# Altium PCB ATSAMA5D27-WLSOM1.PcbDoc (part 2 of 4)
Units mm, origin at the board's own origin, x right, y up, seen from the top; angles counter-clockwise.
Board outline 40.8 x 40.8 mm, 6 copper layers (L1 - Top, L2 - GND, L3 - Signal, L4 - Signal, L5 - PWR, L6 - Bottom), stack 1.144 mm thick; 196 components, 221 nets, 1038 pads, 713 vias.
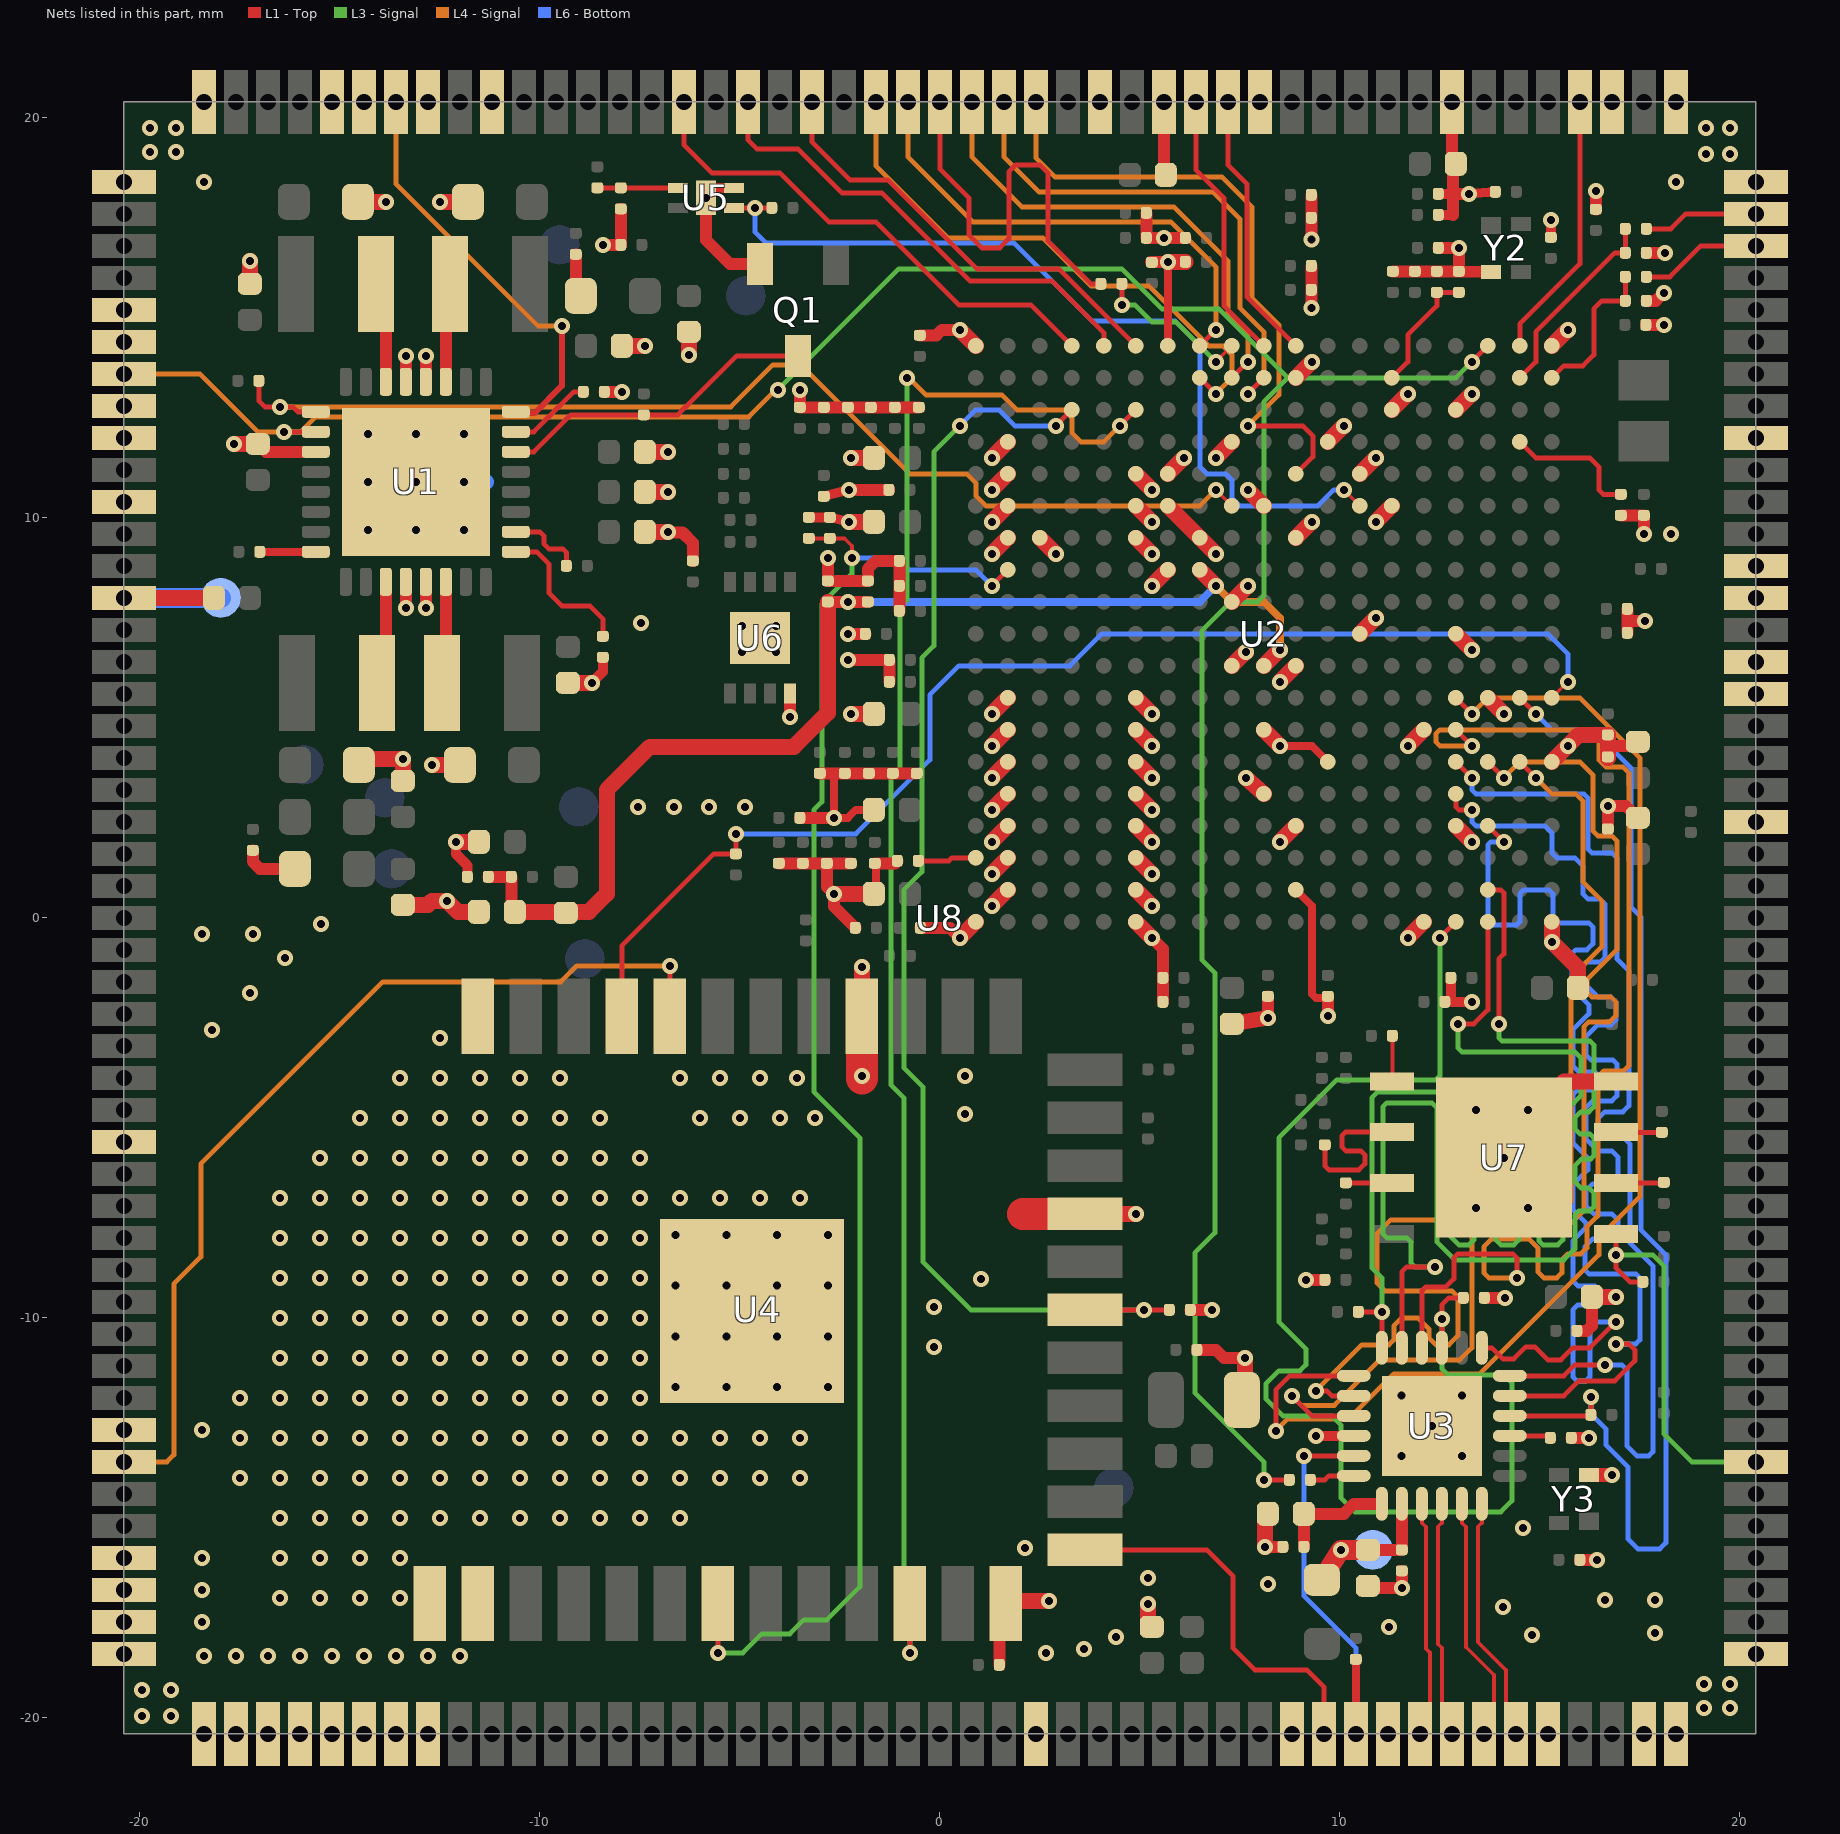
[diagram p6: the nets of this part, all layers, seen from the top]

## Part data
C1 C3 C4 C6 C8 C10 C12 C13 C14 C15 C20 C21 C22 C23 C25 C64 C65 C82 C97 C98 C99 C100 C101 C105: library part CAP1684, "Capacitor", Manufacturer 1="TDK Corporation", Manufacturer Part Number 1=C1005X5R1A475K050BC, Operating Temperature="-55C to 85C", Package=0402, Supplier Part Number 1=445-13820-1-ND, Temperature Coeffcient=X5R, Tolerance=10%, Voltage=10V
C2 C5 C7 C9: library part CAP1648, "Capacitor", Manufacturer 1="TDK Corporation", Manufacturer 2="Murata Electronics North America", Manufacturer Part Number 1=C1608X5R1A226M080AC, Manufacturer Part Number 2=GRM188R61A226ME15D, Operating Temperature="-55C to +85C", Package=0603, Supplier Part Number 1=2525091, Temperature Coeffcient=X5R, Tolerance=20%, Voltage=10V
C11 C16 C24 C26 C27 C28 C29 C30 C31 C32 C33 C34 C35 C36 C37 C38 C39 C40 C41 C42 C43 C44 C45 C46 C47 C48 C49 C50 C51 C52 C53 C54 C55 C56 C57 C58 C59 C60 C61 C62 C63 C66 C67 C68 C69 C70 C71 C72 C73 C74 C75 C76 C77 C78 C79 C80 C81 C83 C85 C87 C89 C90 C92 C93 C94 C95 C96: library part CAP2003, "Capacitor", Manufacturer 1=KEMET, Manufacturer 2="Murata Electronics North America", Manufacturer 3=Yageo, Manufacturer Part Number 1=C0201C104K9PACTU, Manufacturer Part Number 2=GRM033R60J104KE19D, Manufacturer Part Number 3=CC0201KRX5R5BB104, Operating Temperature="-55C to +85C", Package=0201, Supplier Part Number 1=399-7743-1-ND, Temperature Coeffcient=X5R, Tolerance=10%, Voltage=6.3V
C17: library part CAP1453, "Capacitor", Manufacturer 1="TDK Corporation", Manufacturer Part Number 1=C0603C0G1E100D030BA, Operating Temperature="-55C to +125C", Package=0201, Supplier Part Number 1=445-4651-2-ND, Temperature Coeffcient=C0G, Tolerance=0.5pF, Voltage=25V
C18 C19: library part CAP1996, "Capacitor", Manufacturer 1="TDK Corporation", Manufacturer 2="Murata Electronics", Manufacturer Part Number 1=CGA1A2C0G1H080D030BA, Manufacturer Part Number 2=GRM0335C1H8R0BA01D, Operating Temperature="-55C to +125C", Package=0201, Supplier Part Number 1=445-12057-1-ND, Temperature Coeffcient=C0G, Tolerance=0.1pF, Voltage=50V
C84: library part CAP1468, "Capacitor", Manufacturer 1="TDK Corporation", Manufacturer 2="Murata Electronics North America", Manufacturer Part Number 1=C1005X7S1A225K050BC, Manufacturer Part Number 2=GRM155C71A225KE11J, Operating Temperature="-55C to +125C", Package=0402, Supplier Part Number 1=445-9097-1-ND, Temperature Coeffcient=X7S, Tolerance=10%, Voltage=10V
C86 C88: library part CAP1766, "Capacitor", Manufacturer 1=Yageo, Manufacturer Part Number 1=CC0402MRX5R5BB106, Operating Temperature="-55°C ~ 85°C", Package=0402, Supplier Part Number 1=311-1729-1-ND, Temperature Coeffcient=X5R, Tolerance=20%, Voltage=6.3V
C91: library part CAP2000, "Capacitor", Manufacturer 1="Murata Electronics North America", Manufacturer 2="Taiyo Yuden", Manufacturer 3=Murata, Manufacturer 4=TDK, Manufacturer Part Number 1=GRM21BR61A476ME15L, Manufacturer Part Number 2=LMK212BBJ476MG-T, Manufacturer Part Number 3=GRM21BR61A476ME15K, Manufacturer Part Number 4=C2012X5R1A476M125AC, Operating Temperature="-55C to +85C", Package=0805, Supplier Part Number 1=490-9961-1-ND, Temperature Coeffcient=X5R, Tolerance=20%, Voltage=10V
C102 C103 C104: library part CAP1450, "Capacitor", Manufacturer 1="Murata Electronics North America", Manufacturer Part Number 1=GRM0335C1E101JA01D, Operating Temperature="-55C to 125C", Package=0201, Supplier Part Number 1=490-3160-1-ND, Temperature Coeffcient=NP0, Tolerance=5%, Voltage=25V
C106 C107: library part CAP1201, "Capacitor", Manufacturer 1=Murata, Manufacturer Part Number 1=GRM033R61A103KA01D, Operating Temperature="-55C to +85C", Package=0201, Supplier Part Number 1=490-3166-2-ND, Temperature Coeffcient=X5R, Tolerance=10%, Voltage=10V
FB1: library part IND1453, "FERRITE 180R 1.5A SMD 0603", Manufacturer 1="Murata Electronics North America", Manufacturer Part Number 1=BLM18PG181SN1D, Operating Temperature="-55C to +125C", Package=0603, Saturation Current=1.5A, Supplier Part Number 1=490-5263-1-ND, Test Frequency=100MHz
FB2: library part IND1453, Manufacturer 1="Murata Electronics North America", Manufacturer Part Number 1=BLM18PG181SN1D, Operating Temperature="-55C to +125C", Package=0603, Saturation Current=1.5A, Supplier Part Number 1=490-5263-1-ND, Test Frequency=100MHz
FB3 FB4: library part IND1642, Manufacturer 1="Wurth Electronics", Manufacturer Part Number 1=742792731, Operating Temperature="-55C to +125C", Package=0402, RMS Current=1.2A, Supplier Part Number 1=732-2362-1-ND, Test Frequency=100MHz
L1 L3 L4 L6: library part IND1335, Manufacturer 1="Murata Electronics North America", Manufacturer Part Number 1=DFE252012P-1R5M{}P2, Package=1008, RMS Current=3.5A, Supplier Part Number 1=490-10648-6-ND, Test Frequency=1MHz
L2 L5: library part IND1213, Manufacturer 1="TDK Corporation", Manufacturer Part Number 1=MLZ1608N100LT000, Operating Temperature="-55C to +125C", Package=0603, RMS Current=300mA, Saturation Current=60mA, Supplier Part Number 1=445-6755-1-ND, Test Frequency=2MHz
Q1: library part TRA1147, "Transistor MOS", Current=220mA, Drain to Source Voltage=50V, Gate to Source Voltage=1.3V, Manufacturer 1=Fairchild, Manufacturer Part Number 1=BSS138, Operating Temperature="-55C to +150C", Package=SOT-23-3, Power=360mW, Supplier Part Number 1=9845330
R1 R27: library part RES1582, Manufacturer 1="Panasonic Electronic Components", Manufacturer Part Number 1=ERJ-1GEF1003C, Operating Temperature="-55C to +125C", Package=0201, Power=1/20W, Supplier Part Number 1=P100KABCT-ND, Temperature Coeffcient=200ppm/C, Tolerance=1%, Voltage=15V
R2 R6 R11 R23 R24 R26 R32 R34 R35 R36 R37 R38 R39 R40 R41: library part RSMT1252, Manufacturer 1=Yageo, Manufacturer Part Number 1=RC0201FR-0710KL, Operating Temperature="-55 to +125C", Package=0201, Power=1/20W, Supplier Part Number 1=311-10.0KMCT-ND, Temperature Coeffcient=200pm/C, Tolerance=1%, Voltage=25V
R3 R20 R21: library part RES1588, Manufacturer 1="Panasonic Electronic Components", Manufacturer Part Number 1=ERJ-1GEF1001C, Operating Temperature="-55°C to 125°C", Package=0201, Power=1/20W, Supplier Part Number 1=P1.00KABTR-ND, Tolerance=1%, Voltage=25V
R4 R8: library part RSMT1253, Manufacturer 1=Yageo, Manufacturer Part Number 1=RC0201JR-072R2L, Operating Temperature="-55C to +125C", Package=0201, Power=1/20W, Supplier Part Number 1=YAG2886CT-ND, Temperature Coeffcient="-100/+350 ppm/C", Tolerance=5%, Voltage=25V
R5 R25 R58 R60: library part RSMT1240, Current=0.5A, Manufacturer 1="Panasonic Electronic Components", Manufacturer Part Number 1=ERJ-1GN0R00C, Operating Temperature="-55C to +125C", Package=0201, Power=1/20W, Supplier Part Number 1=P15979CT-ND, Voltage=50V
R9 R10: library part RES2022, Manufacturer 1=Yageo, Manufacturer Part Number 1=RC0402FR-071K5L, Operating Temperature="-55C to +155C", Package=0402, Power=1/16W, Supplier Part Number 1=311-1.50KLRCT-ND, Temperature Coeffcient=100ppm/°C, Tolerance=1%
R12: library part RES2053, Manufacturer 1=Yageo, Manufacturer Part Number 1=RC0201FR-075K62L, Operating Temperature="-55C to +125C", Package=0201, Power=1/20W, Supplier Part Number 1=YAG2345CT-ND, Temperature Coeffcient=200ppm/C, Tolerance=1%
R13 R14 R42 R43: library part RSMT1251, Current=0.5A, Manufacturer 1="Vishay Dale", Manufacturer Part Number 1=CRCW02012K20FKED, Operating Temperature="-55C to +155C", Package=0201, Power=1/20W, Supplier Part Number 1=541-2.20KAABCT-ND, Temperature Coeffcient=100ppm/C, Tolerance=1%, Voltage=25V
R15 R16 R17 R18 R44 R45 R46 R47 R48 R49 R50 R51 R52 R53 R59: library part RES1473, Manufacturer 1="Panasonic Electronic Components", Manufacturer Part Number 1=ERJ-1GEF22R0C, Operating Temperature="-55C to +125C", Package=0201, Power=1/20W, Supplier Part Number 1=P22.0ABCT-ND, Tolerance=1%, Voltage=25V
R19: library part RSMT1249, Current=0.5A, Manufacturer 1=Yageo, Manufacturer Part Number 1=RC0201FR-07240RL, Operating Temperature="-55C to +125C", Package=0201, Power=1/20W, Supplier Part Number 1=YAG2528CT-ND, Temperature Coeffcient=200ppm, Tolerance=1%, Voltage=25V
R22: library part RSMT1250, Current=0.5A, Manufacturer 1=Yageo, Manufacturer Part Number 1=AC0201FR-076K49L, Operating Temperature="-55C to +155C", Package=0201, Power=1/20W, Supplier Part Number 1=YAG5236CT-ND, Temperature Coeffcient=200ppm, Tolerance=1%, Voltage=25V
R28 R29 R30 R31: library part RES2264, Manufacturer 1=Yageo, Manufacturer Part Number 1=RC0201FR-0768KL, Operating Temperature="-55C to +125C", Package=0201, Power=1/20W, Supplier Part Number 1=YAG2772CT-ND, Temperature Coeffcient=200ppm/C, Tolerance=1%, Voltage=25V
R55 R56 R57: library part RES2175, Current=0.5A, Manufacturer 1=Yageo, Manufacturer Part Number 1=RC0201FR-07100RL, Operating Temperature="-55C to +125C", Package=0201, Power=1/20W, Supplier Part Number 1=311-100MCT-ND, Temperature Coeffcient=200ppm/C, Tolerance=1%, Voltage=25V
TP1 TP2 TP3 TP4 TP6 TP7 TP8 TP9 TP10 TP11: library part CON1759, "Test Point"
U1: library part MIC8644, Manufacturer 1="Microchip Technology", Manufacturer Part Number 1=MCP16502AC-E/S8B
U2: library part MIC8130, "SAMA5D2 MPU with 2Gb LPDDR2 x32 TFBGA-361", Manufacturer 1="Microchip Technology / Atmel", Manufacturer Part Number 1=ATSAMA5D27C-LD2G-CU, PackageType=TFBGA-361, PackageWidth=16x16x1.2mm, Supplier Part Number 1=ATSAMA5D27C-LD2G-CU-ND, TempRange="-40C to +85C"
U3: library part MIC7404, Manufacturer 1="Microchip Technology", Manufacturer Part Number 1=KSZ8081RNAIA-TR, Supplier Part Number 1=576-4174-1-ND
U4: library part MIC8126, FrequencyRange="2.412-2.472 MHz", Manufacturer 1="Microchip Technology", Manufacturer Part Number 1=ATWILC3000-MR110UA, PowerRX="84mA (802.11n MCS7)", PowerTX="253mA (802.11n MCS7)", RfPower=0, Supplier Part Number 1=ATWILC3000-MR110UA-ND
U5: library part MIC8024, Manufacturer 1="Microchip Technology", Manufacturer Part Number 1=MIC842NYMT-T5, PackageType=UDFN, PackageWidth=1.2x1.6x0.6mm, Supplier Part Number 1=576-4506-1-ND, TempRange="-40C to +85C"
U6: library part MIC8843, Manufacturer 1="Microchip Technology Inc", Manufacturer Part Number 1=ATECC608A-TNGTLSU-C, Supplier Part Number 1=150-ATECC608A-TNGTLSU-C-ND
U7: library part MIC8649, "SQI Serial Flash", Manufacturer 1="Microchip Technology", Manufacturer Part Number 1=SST26VF064BEUI-104I/MF, MaxClockFreq="104 MHz", OpVoltMax=3,6, OpVoltMin=2,3, PackageType=TDFN-S, PackageWidth=6x5x0.8mm, TempRange="-40C to +85C"
U8: library part WLSOM-188, "188-Castellated thru-holes, 40.80mm x 40.80mm package"
Y1: library part OSC1206, "Crystal", Load Capacitance=6pF, Manufacturer 1="NDK America, Inc.", Manufacturer Part Number 1=NX2012SA-32.768KHZ-EXS00A-MU00626, Operating Temperature="-40C to +85C", Package="2mm x 1.2mm", Supplier Part Number 1=644-1355-1-ND, Tolerance="20 ppm"
Y2: library part MIC8647, Manufacturer 1="Microchip Technology", Manufacturer Part Number 1=DSC6003HI2B-024.0000, Supplier Part Number 1=DSC6003HI2B-024.0000-ND
Y3: library part MIC8785, Manufacturer 1="Microchip Technology Inc", Manufacturer Part Number 1=DSC6102HI2B-025.000

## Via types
v1: diameter 0.4, hole 0.2, L1 - Top to L6 - Bottom, 680 vias
v2: diameter 0.4, hole 0.2, L1 - Top to L6 - Bottom, tented both sides, 17 vias
v3: diameter 0.4, hole 0.2, L1 - Top to L6 - Bottom, tented bottom, 16 vias

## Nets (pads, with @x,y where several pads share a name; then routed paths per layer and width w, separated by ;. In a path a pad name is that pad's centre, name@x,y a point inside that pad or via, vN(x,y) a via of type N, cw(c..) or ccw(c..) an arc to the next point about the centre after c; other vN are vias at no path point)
CE_WILC_PA29: R34.2 U2.U16 U4.19 | length 33.2
  L1 - Top w0.125: v1(2.9,12.3) U2.U16@3.3,12.7 ; U4.19@3.53,-9.8 U4.19@3.63,-9.8 v1@5,-9.8 ; v1@5.2,-9.8 R34.2@5.738,-9.8
  L3 - Signal w0.125: v1(0.5,12.3) -0.15,11.65 -0.15,6.8 -0.45,6.5 -0.45,1.15 -0.9,0.7 -0.9,-3.75 -0.425,-4.225 -0.425,-8.6 0.775,-9.8 v1(5.1,-9.8) ; v1@5,-9.8 v1(5.1,-9.8) ; v1@5.1,-9.75 v1(5.1,-9.8)
  L6 - Bottom w0.125: v1(0.5,12.3) 0.9,12.7 1.475,12.7 1.875,12.3 v1(2.9,12.3)
CLK_AUDIO: U2.W2 U8.145 | length 6.7
  L1 - Top w0.125: U2.W2@14.5,14.3 14.5,14.85 16,16.35 U8.145@16,20.4
COMPN: C103.2 R56.2 U2.V2 | length 5
  L1 - Top w0.125: U2.V2@14.5,13.5 14.9,13.9 14.9,14.65 16.875,16.625 C103.2@17.138,16.625 R56.2@17.138,17.225
COMPP: C102.2 R55.2 U2.V1 | length 3.9
  L1 - Top w0.125: U2.V1@15.3,13.5 15.6,13.8 16.075,13.8 16.35,14.075 16.35,15.225 16.55,15.425 C102.2@17.138,15.425 R55.2@17.138,16.025
CTS_WILC_PA26: U2.U14 U4.11 | length 40.6
  L1 - Top w0.125: v1(-0.75,-18.375) U4.11@-0.75,-17.14 ; v1(4.5,12.3) U2.U14@4.9,12.7
  L3 - Signal w0.125: v1(-0.825,13.5) -0.825,7.95 -1,7.775 -1,3.675 -1.225,3.45 -1.225,-4.175 -0.9,-4.5 -0.9,-17.6 -0.75,-17.75 v1(-0.75,-18.375) ; v1(4.5,12.3) v1@4.6,12.2
  L4 - Signal w0.125: v1(-0.825,13.5) -0.775,13.5 -0.35,13.075 1.55,13.075 1.925,12.7 3.1,12.7 3.3,12.5 3.3,12.125 3.525,11.9 4.1,11.9 v1(4.5,12.3)
DDR_VREF: C11.1 C16.2 C61.1 C62.1 R9.1 R10.2 U2.J10 U2.M12 | length 29.9
  L1 - Top w0.3: C16.2@-11.288,1.025 C11.1@-10.712,1.025 -10.712,0.237 R10.2@-10.625,0.15 ; C62.1@-2.8,7.9 v1(-2.3,7.9) C61.1@-1.8,7.9
  L1 - Top w0.4: R10.2@-10.625,0.15 -8.775,0.15 -8.325,0.6 -8.325,3.2 -7.25,4.275 -3.65,4.275 -2.8,5.125 C62.1@-2.8,7.9 ; U2.M12@6.5,8.7 v1(6.9,8.3) ; U2.J10@8.1,6.3 v1(8.5,6.7)
  L4 - Signal w0.2: v1(6.9,8.3) 7.3,7.9 8.1,7.9 8.5,7.5 v1(8.5,6.7)
  L6 - Bottom w0.2: v1(-2.3,7.9) 6.5,7.9 v1(6.9,8.3)
ETH_GMDC_PB22: U2.E4 U3.11 | length 28.1
  L1 - Top w0.125: U2.E4@12.9,3.1 12.9,2.775 12.975,2.7 v1(13.3,2.7) ; U3.11@14.25,-11.95 15.6,-11.95 15.975,-11.575 16.875,-11.575 17.375,-11.075 17.375,-10.8 17.225,-10.65 v1(16.9,-10.65)
  L6 - Bottom w0.125: v1(13.3,2.7) 13.3,2.4 13.4,2.3 15.125,2.3 15.3,2.125 15.3,1.625 15.425,1.5 15.875,1.5 16.075,1.3 16.075,0.6 16.2,0.475 16.5,0.475 16.625,0.35 16.625,-1 16.525,-1.1 16.175,-1.1 16.075,-1.2 16.075,-1.6 16.45,-1.975 16.775,-1.975 16.9,-2.1 16.9,-2.55 16.775,-2.675 16.45,-2.675 16.15,-2.975 16.15,-3.425 16.275,-3.55 16.825,-3.55 16.925,-3.65 16.925,-4.45 16.8,-4.575 16.325,-4.575 16.15,-4.75 16.15,-5.525 16.45,-5.825 16.8,-5.825 16.95,-5.975 16.95,-6.5 16.8,-6.65 16.325,-6.65 16.15,-6.825 16.15,-7.2 16.35,-7.4 16.8,-7.4 16.95,-7.55 16.95,-7.85 16.775,-8.025 16.325,-8.025 16.125,-8.225 16.125,-8.8 16.225,-8.9 17.4,-8.9 17.5,-9 17.5,-10.55 17.4,-10.65 v1(16.9,-10.65)
ETH_GMDIO_PB23: R21.1 U2.H2 U3.10 | length 30.8
  L1 - Top w0.125: U3.10@14.25,-12.45 R21.1@16.3,-12.45 ; U2.H2@14.5,5.5 v1(14.9,5.1) ; R21.1@16.275,-12.425 v1(16.275,-11.975)
  L6 - Bottom w0.125: v1(14.9,5.1) 15.3,4.7 16.325,4.7 17.275,3.75 17.275,0.275 17.525,0.025 17.525,-7.8 18.15,-8.425 18.15,-15.625 18,-15.775 17.45,-15.775 17.2,-15.525 17.2,-13.725 16.65,-13.175 16.65,-12.775 16.275,-12.4 v1(16.275,-11.975)
ETH_GRX0_PB18: U2.D3 U3.13 | length 28.3
  L1 - Top w0.125: U3.13@13.55,-10.75 13.8,-10.75 14.075,-11.025 14.35,-11.025 14.65,-10.725 14.875,-10.725 15.2,-11.05 15.525,-11.05 15.825,-10.75 16.25,-10.75 v1(16.9,-10.1) ; U2.D3@13.7,2.3 v1(14.1,1.9)
  L6 - Bottom w0.125: v1(14.1,1.9) 13.775,1.9 13.7,1.825 13.7,-0.075 13.8,-0.175 14.425,-0.175 14.5,-0.1 14.5,0.6 14.6,0.7 15.225,0.7 15.325,0.6 15.325,-0.025 15.425,-0.125 16.225,-0.125 16.325,-0.225 16.325,-0.65 16.175,-0.8 15.9,-0.8 15.8,-0.9 15.8,-1.75 16.225,-2.175 16.225,-2.4 15.825,-2.8 15.825,-3.7 15.975,-3.85 16.375,-3.85 16.475,-3.95 16.475,-4.2 16.375,-4.3 15.95,-4.3 15.825,-4.425 15.825,-5.625 16.2,-6 16.2,-6.3 15.825,-6.675 15.825,-7.3 16.15,-7.625 16.15,-7.75 15.825,-8.075 15.825,-9.075 15.95,-9.2 16.375,-9.2 16.475,-9.3 16.475,-9.575 16.375,-9.675 15.95,-9.675 15.825,-9.8 15.825,-11.475 15.925,-11.575 16.15,-11.575 16.25,-11.475 16.25,-10.2 16.35,-10.1 v1(16.9,-10.1)
ETH_GRX1_PB19: U2.F4 U3.12 | length 28.2
  L1 - Top w0.125: U2.F4@12.9,3.9 v1(13.3,3.5) ; U3.12@14.25,-11.45 15.6,-11.45 15.875,-11.175 v1(16.625,-11.175)
  L6 - Bottom w0.125: v1(13.3,3.5) 13.3,3.2 13.4,3.1 16.1,3.1 16.2,3 16.2,1.725 16.3,1.625 16.8,1.625 16.925,1.5 16.925,-1.025 17.225,-1.325 17.225,-4.7 17.075,-4.85 16.625,-4.85 16.45,-5.025 16.45,-5.375 16.575,-5.5 17.1,-5.5 17.25,-5.65 17.25,-8.125 17.825,-8.7 17.825,-13.35 17.725,-13.45 17.425,-13.45 17.175,-13.2 17.175,-11.3 17.05,-11.175 v1(16.625,-11.175)
ETH_GRXDV_PB16: R23.2 U2.A4 U3.15 | length 32.5
  L1 - Top w0.125: v1(12.5,-0.5) U2.A4@12.9,-0.1 ; U3.15@12.55,-10.75 v1(12.55,-10.025) 12.55,-9.675 12.725,-9.5 R23.2@13.088,-9.5
  L3 - Signal w0.125: v1(12.5,-0.5) 12.5,-3.95 12.4,-4.05 9.925,-4.05 8.475,-5.5 8.475,-10.1 9.15,-10.775 9.15,-11.175 9,-11.325 8.475,-11.325 8.15,-11.65 8.15,-12.025 8.575,-12.45 9.8,-12.45 10.025,-12.675 10.025,-14.5 10.375,-14.85 14.025,-14.85 14.3,-14.575 14.3,-11.625 14.1,-11.425 12.7,-11.425 12.55,-11.275 v1(12.55,-10.025)
ETH_GRXER_PB17: U2.B3 U3.17 | length 29.8
  L1 - Top w0.125: U3.17@11.55,-10.75 11.55,-8.85 11.675,-8.725 v1(12.375,-8.725) ; U2.B3@13.7,0.7 14.025,0.7 14.1,0.625 14.1,-0.9 13.975,-1.025 v1(13.975,-2.65)
  L3 - Signal w0.125: v1(12.375,-8.725) 11.875,-8.725 11.775,-8.625 11.775,-8.1 11.675,-8 11.175,-8 11.075,-7.9 11.075,-4.725 11.175,-4.625 12.3,-4.625 12.425,-4.75 12.425,-8.1 12.875,-8.55 15.6,-8.55 15.875,-8.275 15.875,-7.425 15.975,-7.325 16.25,-7.325 16.35,-7.225 16.35,-6.875 16.225,-6.75 16.025,-6.75 15.875,-6.6 15.875,-6.2 16.05,-6.025 16.275,-6.025 16.35,-5.95 16.35,-5.5 16.25,-5.4 16,-5.4 15.875,-5.275 15.875,-5 16.025,-4.85 16.225,-4.85 16.35,-4.725 16.35,-3.175 16.25,-3.075 14.05,-3.075 13.975,-3 v1(13.975,-2.65)
ETH_GTX0_PB20: U2.F2 U3.20 | length 31.4
  L1 - Top w0.125: v1(9.4,-11.825) 9.675,-11.825 9.8,-11.95 U3.20@10.35,-11.95 ; U2.F2@14.5,3.9 v1(14.9,3.5)
  L4 - Signal w0.125: v1(9.4,-11.825) 10.55,-10.675 11.225,-10.675 11.35,-10.55 11.35,-10.2 11.55,-10 11.95,-10 12.225,-10.275 12.225,-10.5 12.4,-10.675 12.725,-10.675 12.95,-10.45 12.95,-9.475 12.8,-9.325 11.125,-9.325 10.925,-9.125 10.925,-7.9 11.275,-7.55 12.425,-7.55 12.625,-7.35 12.625,-6.225 13.275,-5.575 13.775,-5.575 14.125,-5.225 14.85,-5.225 15.025,-5.4 15.025,-7.05 15.225,-7.25 15.625,-7.25 15.775,-7.1 15.775,-1.5 16.55,-0.725 16.55,0.425 16.075,0.9 16.075,2.925 15.9,3.1 15.3,3.1 v1(14.9,3.5)
ETH_GTX1_PB21: U2.F3 U3.21 | length 31.4
  L1 - Top w0.125: v1(8.8,-11.95) 9.3,-12.45 U3.21@10.35,-12.45 ; U2.F3@13.7,3.9 v1(14.1,3.5)
  L4 - Signal w0.125: v1(8.8,-11.95) 9.038,-12.188 9.862,-12.188 11,-11.05 13,-11.05 13.3,-10.75 13.3,-7.85 12.975,-7.525 12.975,-6.725 13.175,-6.525 13.9,-6.525 14.05,-6.675 14.05,-7.475 14.275,-7.7 15.725,-7.7 16.1,-7.325 16.1,-2.725 16.225,-2.6 16.75,-2.6 16.9,-2.45 16.9,-2.1 16.775,-1.975 16.3,-1.975 16.175,-1.85 16.175,-1.55 16.925,-0.8 16.925,1.925 16.8,2.05 16.45,2.05 16.325,2.175 16.325,3.575 16,3.9 14.5,3.9 v1(14.1,3.5)
ETH_GTXCK_PB14: U2.G4 U3.16 | length 30.4
  L1 - Top w0.125: U3.16@12.05,-10.75 12.05,-9.325 12.15,-9.225 12.65,-9.225 12.85,-9.025 12.85,-8.5 12.95,-8.4 14.325,-8.4 14.425,-8.5 v1(14.425,-9) ; U2.G4@12.9,4.7 v1(13.3,4.3)
  L4 - Signal w0.125: v1(13.3,4.3) 12.5,4.3 12.4,4.4 12.4,4.6 12.5,4.7 16.25,4.7 16.475,4.475 16.475,3.95 16.65,3.775 17.075,3.775 17.225,3.625 17.225,-3.7 17.1,-3.825 16.6,-3.825 16.45,-3.975 16.45,-7.45 16.175,-7.725 16.175,-8.25 16.025,-8.4 15.7,-8.4 15.55,-8.55 15.55,-8.875 15.425,-9 15.1,-9 14.95,-8.85 14.95,-8.25 14.725,-8.025 13.8,-8.025 13.6,-8.225 13.6,-8.875 13.725,-9 v1(14.425,-9)
ETH_GTXEN_PB15: U2.H4 U3.19 | length 31.4
  L1 - Top w0.125: v1(8.4,-12.825) 8.4,-11.8 8.75,-11.45 U3.19@10.35,-11.45 ; U2.H4@12.9,5.5 v1(13.3,5.1)
  L4 - Signal w0.125: v1(8.4,-12.825) 8.7,-12.525 10.225,-12.525 11.35,-11.4 13.5,-11.4 16.475,-8.425 16.475,-8 17.5,-6.975 17.5,4 16,5.5 13.7,5.5 v1(13.3,5.1)
ETH_INT_PB24: R20.1 U2.A3 U3.18 | length 29.8
  L1 - Top w0.125: R20.1@10.462,-9.85 v1(11.05,-9.85) U3.18@11.05,-10.75 ; v1(12.95,-2.65) 13.35,-2.65 13.7,-2.3 U2.A3@13.7,-0.1
  L3 - Signal w0.125: v1(11.05,-9.85) 11.05,-9 10.8,-8.75 10.8,-4.5 10.95,-4.35 12.575,-4.35 12.725,-4.5 12.725,-7.925 12.975,-8.175 13.225,-8.175 13.35,-8.05 13.35,-7.8 13.475,-7.675 13.775,-7.675 13.9,-7.8 13.9,-8.05 14.025,-8.175 14.35,-8.175 14.475,-8.05 14.475,-7.775 14.575,-7.675 14.85,-7.675 14.975,-7.8 14.975,-8.075 15.075,-8.175 15.45,-8.175 15.575,-8.05 15.575,-7.4 15.5,-7.325 15.225,-7.325 15.125,-7.225 15.125,-6.85 15.225,-6.75 15.45,-6.75 15.575,-6.625 15.575,-6.15 15.45,-6.025 15.25,-6.025 15.125,-5.9 15.125,-5.525 15.25,-5.4 15.475,-5.4 15.575,-5.3 15.575,-4.75 15.7,-4.625 15.85,-4.625 16.025,-4.45 16.025,-3.5 15.875,-3.35 13.05,-3.35 12.95,-3.25 v1(12.95,-2.65)
ETH_LED0: R24.1 U3.23 U8.84 | length 10.5
  L1 - Top w0.125: v1(9.1,-13.45) U3.23@10.35,-13.45
  L1 - Top w0.2: U8.84@10.4,-20.4 R24.1@10.4,-18.537
  L6 - Bottom w0.125: v1(9.1,-13.45) 9.1,-16.95 10.4,-18.25 U8.84@10.4,-20.3
ETH_RX_N: U3.3 U8.86 | length 5.9
  L1 - Top w0.1: U8.86@12,-20.4 12.25,-20.15 12.25,-18.374 12.15,-18.274 12.15,-15.225 12.05,-15.125 U3.3@12.05,-14.65
ETH_RX_P: U3.4 U8.87 | length 5.9
  L1 - Top w0.1: U3.4@12.55,-14.65 12.55,-15.125 12.45,-15.225 12.45,-18.15 12.55,-18.25 12.55,-20.15 U8.87@12.8,-20.4
ETH_TX_N: U3.5 U8.88 | length 6.2
  L1 - Top w0.1: U3.5@13.05,-14.65 13.05,-15.125 13.15,-15.225 13.15,-18.225 13.85,-18.925 13.85,-20.15 U8.88@13.6,-20.4
ETH_TX_P: U3.6 U8.89 | length 6.2
  L1 - Top w0.1: U3.6@13.55,-14.65 13.55,-15.125 13.45,-15.225 13.45,-18.101 14.15,-18.801 14.15,-20.15 U8.89@14.4,-20.4
GND: C1.1 C2.2 C3.1 C4.1 C5.2 C6.1 C7.2 C8.1 C9.2 C10.1 C12.1 C13.1 C14.1 C15.1 C16.1 C17.1 C18.1 C19.1 C20.2 C21.2 C22.2 C23.2 C24.2 C25.2 C26.2 C27.2 C28.2 C29.2 C30.2 C31.2 C32.2 C33.2 C34.2 C35.2 C36.2 C37.2 C38.1 C39.2 C40.2 C41.2 C42.2 C43.2 C44.2 C45.2 C46.2 C47.2 C48.2 C49.2 C50.2 C51.2 C52.2 C53.2 C54.2 C55.2 C56.2 C57.2 C58.2 C59.2 C60.2 C61.2 C62.2 C63.2 C64.2 C65.2 C66.2 C67.2 C68.2 C69.2 C70.2 C71.2 C72.2 C73.2 C74.2 C75.2 C76.2 C77.2 C78.2 C79.2 C80.2 C81.2 C82.2 C83.2 C84.2 C85.2 C86.1 C87.1 C88.1 C89.1 C90.1 C91.1 C92.1 C93.1 C94.1 C95.1 C96.1 C97.1 C98.1 C99.1 C100.2 C101.2 C102.1 C103.1 C104.1 C105.1 C106.1 C107.2 Q1.2 R2.2 R5.2 R10.1 R11.1 R12.1 R19.2 R22.1 R23.1 R34.1 R35.1 R60.2 TP4.1 U1.3 U1.12 U1.13 U1.28 U1.29 U1.33 U2.A1 U2.A5 U2.A14 U2.A19 U2.B9 U2.B14 U2.B18 U2.C14 U2.C18 U2.D4 U2.D9 U2.D14 U2.D18 U2.E10 U2.E14 U2.E18 U2.F1 U2.F8 U2.F14 U2.F18 U2.G5 U2.G10 U2.G14 U2.G18 U2.H3 U2.H14 U2.H18 U2.J9 U2.J11 U2.K4 U2.K7 U2.L11 U2.M13 U2.N9 U2.N12 U2.N14 U2.N17 U2.N18 U2.P6 U2.P10 U2.P13 U2.P14 U2.P18 U2.R7 U2.R13 U2.R14 U2.R18 U2.T8 U2.T11 U2.T18 U2.U4 U2.U6 U2.V9 U2.W1 U2.W13 U2.W19 U3.22 U3.25 U4.1 U4.2 U4.13 U4.21 U4.28 U4.36 U4.37 U5.2 U5.EP U6.4 U6.9 U7.4 U7.9 U8.1 U8.5 U8.6 U8.8 U8.9 U8.11 U8.14 U8.31 U8.40 U8.44 U8.45 U8.46 U8.47 U8.48 U8.49 U8.50 U8.51 U8.52 U8.53 U8.54 U8.55 U8.74 U8.82 U8.85 U8.90 U8.93 U8.94 U8.95 U8.121 U8.125 U8.126 U8.128 U8.129 U8.133 U8.141 U8.142 U8.144 U8.149 U8.155 U8.158 U8.160 U8.179 U8.181 U8.183 U8.184 U8.188 Y2.2 Y3.2 | length 143.6
  L1 - Top w0.2: -2.65,3.613 v1(-2.65,2.5) -2.3,2.5 -2.1,2.7 C21.2@-1.65,2.7 ; C65.2@-1.6,0.6 C70.2@-1.6,1.3 ; U2.W13@5.7,14.3 v1(5.7,16.4) ; U2.L11@7.3,7.9 U2.L11@7.3,7.95 ; v1(8.5,4.3) 9.3,4.3 U2.F8@9.7,3.9 ; U2.B9@8.9,0.7 9.3,0.3 9.3,-1.9 9.4,-2 C57.2@9.7,-2
  L1 - Top w0.25: v1(-12.1,1.9) -12.1,1.6 -11.812,1.312 C16.1@-11.812,1.025 ; v1(-8.7,5.875) -8.425,6.15 R5.2@-8.425,6.513 ; U5.EP@-5.85,18.25 U5.2@-5.15,18.25 ; C106.1@-3.275,10.012 R35.1@-2.75,10.012 v1(-2.275,9.9) ; C42.2@-2.9,10.538 v1(-2.275,10.7) ; v1(9.4,-12.95) U3.22@10.35,-12.95 ; C107.2@12.462,17.575 12.825,17.575 ; C83.2@12.462,18.1 12.825,18.1 ; C48.2@12.775,-1.5 12.775,-2.075 12.8,-2.1 v1(13.3,-2.1) ; v1(13.225,18.1) C38.1@13.888,18.15 ; R60.2@15.275,17.012 v1(15.275,17.45)
  L1 - Top w0.3: C10.1@-17.05,11.85 -16.85,11.65 U1.3@-15.6,11.65 ; v1(-13.35,7.75) U1.12@-13.35,8.4 ; U1.29@-13.35,13.4 v1(-13.35,14.05) ; v1(-12.85,7.75) U1.13@-12.85,8.4 ; U1.28@-12.85,13.4 v1(-12.85,14.05) ; v1(-8.425,16.825) C94.1@-7.975,16.825 C104.1@-7.975,17.725 ; R2.2@-8.388,13.15 v1(-7.95,13.15) ; v1(-6.8,9.65) -6.781,9.631 -6.431,9.631 -6.175,9.375 C95.1@-6.175,8.925 ; v2(-5.85,18) -5.85,16.95 -5.25,16.35 Q1.2@-4.5,16.35 ; C45.2@-4.025,1.363 C49.2@-3.425,1.363 C52.2@-2.825,1.363 ; v1(-3.75,5.025) U6.4@-3.75,5.602 ; C31.2@-3.5,2.5 v1(-2.65,2.5) ; v1(-3.5,13.2) C39.2@-3.5,12.762 C37.2@-2.9,12.762 C54.2@-2.3,12.762 C55.2@-1.725,12.762 C56.2@-1.125,12.762 C59.2@-0.525,12.762 ; C50.2@-3,3.613 -2.65,3.613 C44.2@-2.375,3.613 C74.2@-1.775,3.613 C47.2@-1.175,3.613 C29.2@-0.575,3.613 ; v1(-2.8,9) C62.2@-2.8,8.425 C61.2@-1.8,8.425 -1.8,8.725 -1.6,8.925 C35.2@-1.012,8.925 C27.2@-1.012,8.3 C58.2@-1.012,7.675 ; v1(-2.3,6.45) C76.2@-1.262,6.45 C71.2@-1.262,5.9 ; v1(-2.3,7.1) C67.2@-1.862,7.1 ; v1(-2.275,10.7) C68.2@-1.275,10.7 ; C33.2@-2.225,1.363 C52.2@-2.825,1.363 ; C73.2@-2.112,-0.25 -2.65,0.288 v1(-2.65,0.6) -2.825,0.775 C52.2@-2.825,1.363 ; C70.2@-1.625,1.363 -1.125,1.363 R19.2@-1.062,1.425 ; C51.2@-0.5,14.562 -0.088,14.562 0.05,14.7 v1(0.5,14.7) ; C41.2@-0.487,-0.25 0.25,-0.25 v1(0.5,-0.5) ; C93.1@1.487,-18.675 1.487,-17.303 U4.13@1.65,-17.14 ; C72.2@5.162,17.625 C79.2@5.162,17 C81.2@6.138,17 ; C40.2@5.275,16.4 v1(5.7,16.4) ; v1(5.3,-0.5) 5.575,-0.775 C78.2@5.575,-1.5 C80.2@5.575,-2.1 ; U8.158@5.6,20.4 5.6,18.625 C101.2@5.65,18.575 ; R34.1@6.262,-9.8 v1(6.8,-9.8) ; C92.1@6.425,-10.8 6.9,-10.8 7.1,-11 v1(7.625,-11) ; v1(8.125,-15.725) C85.2@8.575,-15.725 ; v1(8.2,-2.5) C34.2@8.2,-1.962 ; v1(9.15,-9.05) C96.1@9.625,-9.05 ; v1(9.287,15.25) C43.2@9.287,15.7 C24.2@9.287,16.3 ; v1(9.287,16.956) C60.2@9.287,17.5 C75.2@9.287,18.075 ; v1(9.7,-2.45) C57.2@9.7,-2 ; C86.1@10.7,-16.7 10.75,-16.75 v1(11.55,-16.75) C87.1@11.55,-16.325 ; C32.2@11.325,16.163 C28.2@11.875,16.163 C17.1@12.425,16.163 R12.1@12.975,16.163 ; C77.2@12.462,16.75 v1(12.975,16.75) R12.1@12.975,16.163 ; U8.149@12.8,20.4 12.8,18.95 C100.2@12.9,18.85 12.825,18.775 12.825,18.1 ; 12.825,17.575 12.825,18.1 ; v1(13.225,18.1) 12.825,18.1 ; R23.1@13.613,-9.5 v1(14.125,-9.5) ; Y2.2@13.775,16.15 R12.1@12.975,16.163 ; R22.1@15.787,-13 v1(16.225,-13) ; C89.1@15.925,-10.325 16.175,-10.325 16.3,-10.2 C88.1@16.3,-9.475 ; C90.1@16,-16.05 v1(16.425,-16.05) ; C66.2@16.4,17.712 v1(16.4,18.175) ; C36.2@16.7,2.225 v1(16.7,2.8) 17.15,2.8 C20.2@17.45,2.5 ; 16.7,4.3 C99.1@17.325,4.3 ; R11.1@17.025,10.063 C19.1@17.6,10.063 v1(17.6,9.6) ; C30.2@17.187,7.125 17.187,7.425 ; C26.2@17.187,7.725 17.187,7.425 ; v1(17.625,7.425) 17.187,7.425 ; C18.1@17.65,14.825 v1(18.1,14.825) ; C102.1@17.662,15.425 17.9,15.425 v1(18.1,15.625) ; C103.1@17.662,16.625 v1(18.125,16.625)
  L1 - Top w0.35: Y3.2@16.225,-13.925 v1(16.8,-13.925)
  L1 - Top w0.4: U8.14@-20.4,8 C1.1@-18.15,8 ; v1(-17.65,11.85) C10.1@-17.05,11.85 ; C8.1@-17.25,15.85 v1(-17.25,16.425) ; C9.2@-14.55,17.9 v1(-13.85,17.9) ; C2.2@-14.525,3.975 v1(-13.425,3.975) C97.1@-13.425,3.425 ; C3.1@-13.425,0.325 -12.8,0.325 -12.7,0.425 v1(-12.325,0.425) -12.05,0.15 R10.1@-11.525,0.15 ; v1(-12.7,3.825) C5.2@-12,3.825 ; v1(-12.5,17.9) C7.2@-11.8,17.9 ; v1(-12.1,1.9) C12.1@-11.525,1.9 ; C4.1@-9.3,5.875 v1(-8.7,5.875) ; C6.1@-7.95,14.3 v1(-7.375,14.3) ; C14.1@-7.375,9.65 v1(-6.8,9.65) ; C13.1@-7.375,10.65 v1(-6.8,10.65) ; C15.1@-7.375,11.65 v1(-6.8,11.65) ; v1(-6.275,14.075) C98.1@-6.275,14.65 ; v1(-2.65,0.6) C65.2@-1.65,0.6 ; v1(-2.275,9.9) C25.2@-1.65,9.9 ; v1(-2.225,5.1) C64.2@-1.65,5.1 ; v1(-2.225,11.5) C23.2@-1.65,11.5 ; U4.28@-1.95,-2.46 v1(-1.95,-1.225) ; v1(0.5,-0.5) U2.A19@0.9,-0.1 ; v1(0.5,14.7) U2.W19@0.9,14.3 ; v1(1.3,0.3) U2.B18@1.7,0.7 ; v1(1.3,1.1) U2.C18@1.7,1.5 ; v1(1.3,1.9) U2.D18@1.7,2.3 ; v1(1.3,2.7) U2.E18@1.7,3.1 ; v1(1.3,3.5) U2.F18@1.7,3.9 ; v1(1.3,4.3) U2.G18@1.7,4.7 ; v1(1.3,5.1) U2.H18@1.7,5.5 ; v1(1.3,9.1) U2.N18@1.7,9.5 ; v1(1.3,9.9) U2.P18@1.7,10.3 ; v1(1.3,10.7) U2.R18@1.7,11.1 ; v1(1.3,11.5) U2.T18@1.7,11.9 ; U4.13@1.65,-17.075 v1(2.725,-17.075) ; U2.N17@2.5,9.5 v1(2.9,9.1) ; U4.21@3.63,-7.4 v1(4.9,-7.4) ; U2.A14@4.9,-0.1 v1(5.3,-0.5) ; U2.B14@4.9,0.7 v1(5.3,0.3) ; U2.C14@4.9,1.5 v1(5.3,1.1) ; U2.D14@4.9,2.3 v1(5.3,1.9) ; U2.E14@4.9,3.1 v1(5.3,2.7) ; U2.F14@4.9,3.9 v1(5.3,3.5) ; U2.G14@4.9,4.7 v1(5.3,4.3) ; U2.H14@4.9,5.5 v1(5.3,5.1) ; U2.N14@4.9,9.5 v1(5.3,9.1) ; U2.P14@4.9,10.3 v1(5.3,9.9) ; U2.R14@4.9,11.1 v1(5.3,10.7) ; v1(5.2,-17.15) 5.2,-17.625 C105.1@5.3,-17.725 ; v1(5.3,8.3) U2.M13@5.7,8.7 ; U2.P13@5.7,10.3 U2.N12@6.5,9.5 v1(6.9,9.1) ; U2.R13@5.7,11.1 v1(6.1,11.5) ; v1(5.7,16.4) C53.2@6.138,16.4 ; v1(6.9,11.5) U2.T11@7.3,11.9 ; C82.2@7.3,-2.65 v1(8.2,-2.5) ; U2.J11@7.3,6.3 v1(7.65,6.65) ; U2.L11@7.3,7.9 v1(7.7,8.3) ; C91.1@7.55,-12.05 7.625,-11.975 v1(7.625,-11) ; v1(7.65,3.5) U2.E10@8.1,3.1 ; v1(7.7,10.7) U2.P10@8.1,10.3 ; U2.G10@8.1,4.7 v1(8.5,4.3) ; v1(8.125,-15.725) 8.125,-14.975 C84.2@8.2,-14.9 ; v1(8.5,1.9) U2.D9@8.9,2.3 ; v1(8.5,5.9) U2.J9@8.9,6.3 ; U2.N9@8.9,9.5 v1(9.3,9.9) ; U2.V9@8.9,13.5 v1(9.3,13.9) ; U2.T8@9.7,11.9 v1(10.1,12.3) ; U2.K7@10.5,7.1 v1(10.9,7.5) ; U2.R7@10.5,11.1 v1(10.9,11.5) ; v1(10.9,9.9) U2.P6@11.3,10.3 ; U2.U6@11.3,12.7 v1(11.7,13.1) ; v1(11.7,-0.5) U2.A5@12.1,-0.1 ; v1(11.7,4.3) U2.G5@12.1,4.7 ; U2.D4@12.9,2.3 v1(13.3,1.9) ; U2.K4@12.9,7.1 v1(13.3,6.7) ; U2.U4@12.9,12.7 v1(13.3,13.1) ; U2.H3@13.7,5.5 v1(14.1,5.1) ; U2.A1@15.3,-0.1 v1(15.3,-0.6) 15.95,-1.25 C22.2@15.95,-1.75 ; U2.F1@15.3,3.9 v1(15.7,4.3) 15.975,4.575 C63.2@16.7,4.575 16.7,4.3 C69.2@16.7,4.025 C69.2@16.7,4 ; U2.W1@15.3,14.3 v1(15.7,14.7) ; U7.9@15.6,-4.09 U7.4@16.9,-4.09 ; C88.1@16.3,-9.475 v1(16.9,-9.475)
  L1 - Top w0.8: v1@-1.95,-4.015 U4.28@-1.95,-2.46 ; 2.075,-7.4 U4.21@3.63,-7.4
  L6 - Bottom w0.4: v1(-11.9,10.9) -11.35,10.9
  L6 - Bottom w0.5: U8.14@-20.4,8 TP4.1@-17.975,8
  other v1: -19.95,-19.95 -19.225,-19.95 19.1,-19.75 19.75,-19.75 -19.95,-19.3 -19.225,-19.3 19.1,-19.15 19.75,-19.15 -18.4,-18.45 -17.6,-18.45 -16.8,-18.45 -16,-18.45 -15.2,-18.45 -14.4,-18.45 -13.6,-18.45 -12.8,-18.45 -12,-18.45 2.65,-18.375 3.6,-18.275 4.4,-17.975 14.8,-17.925 17.875,-17.875 11.225,-17.725 -18.45,-17.6 14.075,-17.225 16.625,-17.05 17.875,-17.05 -16.5,-17 -15.5,-17 -14.5,-17 -13.5,-17 -18.45,-16.8 8.2,-16.65 5.2,-16.5 -18.45,-16 -16.5,-16 -15.5,-16 -14.5,-16 -13.5,-16 2.125,-15.75 14.575,-15.25 -16.5,-15 -15.5,-15 -14.5,-15 -13.5,-15 -12.5,-15 -11.5,-15 -10.5,-15 -9.5,-15 -8.5,-15 -7.5,-15 -6.5,-15 -17.5,-14 -16.5,-14 -15.5,-14 -14.5,-14 -13.5,-14 -12.5,-14 -11.5,-14 -10.5,-14 -9.5,-14 -8.5,-14 -7.5,-14 -6.5,-14 -5.5,-14 -4.5,-14 -3.5,-14 11.538,-13.462 13.062,-13.462 -17.5,-13 -16.5,-13 -15.5,-13 -14.5,-13 -13.5,-13 -12.5,-13 -11.5,-13 -10.5,-13 -9.5,-13 -8.5,-13 -7.5,-13 -6.5,-13 -5.5,-13 -4.5,-13 -3.5,-13 -18.45,-12.8 12.3,-12.7 -17.5,-12 -16.5,-12 -15.5,-12 -14.5,-12 -13.5,-12 -12.5,-12 -11.5,-12 -10.5,-12 -9.5,-12 -8.5,-12 -7.5,-12 11.538,-11.938 13.062,-11.938 -16.5,-11 -15.5,-11 -14.5,-11 -13.5,-11 -12.5,-11 -11.5,-11 -10.5,-11 -9.5,-11 -8.5,-11 -7.5,-11 -0.15,-10.725 -16.5,-10 -15.5,-10 -14.5,-10 -13.5,-10 -12.5,-10 -11.5,-10 -10.5,-10 -9.5,-10 -8.5,-10 -7.5,-10 -0.15,-9.725 1.025,-9.025 -16.5,-9 -15.5,-9 -14.5,-9 -13.5,-9 -12.5,-9 -11.5,-9 -10.5,-9 -9.5,-9 -8.5,-9 -7.5,-9 -16.5,-8 -15.5,-8 -14.5,-8 -13.5,-8 -12.5,-8 -11.5,-8 -10.5,-8 -9.5,-8 -8.5,-8 -7.5,-8 13.4,-7.25 14.7,-7.25 -16.5,-7 -15.5,-7 -14.5,-7 -13.5,-7 -12.5,-7 -11.5,-7 -10.5,-7 -9.5,-7 -8.5,-7 -7.5,-7 -6.5,-7 -5.5,-7 -4.5,-7 -3.5,-7 -15.5,-6 -14.5,-6 -13.5,-6 -12.5,-6 -11.5,-6 -10.5,-6 -9.5,-6 -8.5,-6 -7.5,-6 14.1,-6 -14.5,-5 -13.5,-5 -12.5,-5 -11.5,-5 -10.5,-5 -9.5,-5 -8.5,-5 -6,-5 -5,-5 -4,-5 -3.125,-5 0.625,-4.9 13.4,-4.8 14.7,-4.8 -13.5,-4 -12.5,-4 -11.5,-4 -10.5,-4 -9.5,-4 -6.5,-4 -5.5,-4 -4.5,-4 -3.575,-4 -1.95,-3.95 0.625,-3.95 -12.5,-3 -18.2,-2.8 -17.25,-1.875 -16.375,-1 -18.45,-0.4 -17.175,-0.4 -15.475,-0.15 -7.55,2.775 -6.65,2.775 -5.775,2.775 -4.875,2.775 -4.95,6.65 -4.1,6.65 -4.95,7.3 -4.1,7.3 -7.475,7.375 18.275,9.6 -14.3,9.7 -13.1,9.7 -11.9,9.7 -14.3,10.9 -13.1,10.9 -14.3,12.1 -13.1,12.1 -11.9,12.1 5.6,17 -18.4,18.4 18.4,18.4 19.15,19.1 19.75,19.1 -19.75,19.15 -19.1,19.15 -19.75,19.75 -19.1,19.75 19.15,19.75 19.75,19.75
  other v3: -6.605,-11.735 -5.335,-11.735 -4.065,-11.735 -2.795,-11.735 -6.605,-10.465 -5.335,-10.465 -4.065,-10.465 -2.795,-10.465 -6.605,-9.195 -5.335,-9.195 -4.065,-9.195 -2.795,-9.195 -6.605,-7.925 -5.335,-7.925 -4.065,-7.925 -2.795,-7.925
HSIC_DATA: U2.W9 U8.156 | length 6.8
  L1 - Top w0.125: U8.156@7.2,20.4 7.2,18.825 7.675,18.35 7.675,15.525 U2.W9@8.9,14.3
HSIC_STROBE: U2.W10 U8.157 | length 6.8
  L1 - Top w0.125: U8.157@6.4,20.4 6.4,18.7 7.1,18 7.1,15.3 U2.W10@8.1,14.3
INT_MCP16502_PC8: R6.1 U1.1 U2.P11 | length 28.3
  L1 - Top w0.1: v1(6.9,10.7) U2.P11@7.3,10.3
  L1 - Top w0.125: R6.1@-17.025,13.425 -17.025,12.925 -16.875,12.775 v1(-16.5,12.775) -16.175,12.775 -16.05,12.65 U1.1@-15.6,12.65
  L4 - Signal w0.125: v1(-16.5,12.775) -5.225,12.775 -4.175,13.825 -3.475,13.825 -0.75,11.1 0.675,11.1 0.9,10.875 0.9,10.55 1.15,10.3 6.5,10.3 v1(6.9,10.7)
INT_MIC842_PD31: R27.1 U2.P7 U5.1 | length 21.9
  L1 - Top w0.1: v1(10.1,10.7) U2.P7@10.5,10.3
  L1 - Top w0.125: U5.1@-5.15,17.75 v1(-4.625,17.75) R27.1@-4.2,17.75
  L6 - Bottom w0.125: v1(-4.625,17.75) -4.625,17.15 -4.35,16.875 1.85,16.875 3.8,14.925 5.875,14.925 6.5,14.3 6.5,11.275 6.675,11.1 7.15,11.1 7.3,10.95 7.3,10.5 7.5,10.3 9.45,10.3 9.85,10.7 v1(10.1,10.7)
INT_WILC_PB25: R26.1 U2.H1 U4.33 | length 31.4
  L1 - Top w0.1: U2.H1@15.3,5.5 v1(15.7,5.9)
  L1 - Top w0.125: U4.33@-7.95,-2.46 -7.95,-0.7 -5.65,1.6 R26.1@-5.1,1.6 v1(-5.1,2.1)
  L6 - Bottom w0.125: v1(-5.1,2.1) -2.1,2.1 -0.25,3.95 -0.25,5.575 0.475,6.3 3.25,6.3 4.05,7.1 15.2,7.1 15.7,6.6 v1(15.7,5.9)
LPM: Q1.3 R1.1 U1.22 | length 8
  L1 - Top w0.125: U1.22@-10.6,11.65 -10.15,11.65 -9.225,12.575 R1.1@-7.4,12.575 -6.55,12.575 -5.075,14.05 Q1.3@-3.55,14.05
NC_3-WILC: U4.14 U8.83 | length 9.6
  L1 - Top w0.125: U4.14@3.63,-15.8 6.675,-15.8 7.325,-16.45 7.325,-18.25 7.875,-18.8 9.175,-18.8 9.6,-19.225 U8.83@9.6,-20.4
NC_20-WILC: U4.32 U8.41 | length 23.9
  L1 - Top w0.125: U4.32@-6.75,-2.46 v1(-6.75,-1.2)
  L4 - Signal w0.125: U8.41@-20.4,-13.6 -19.325,-13.6 -19.15,-13.425 -19.15,-9.15 -18.475,-8.475 -18.475,-6.15 -13.925,-1.6 -9.475,-1.6 -9.075,-1.2 v1(-6.75,-1.2)
NCS_QSPI: R36.1 U7.1 U8.101 | length 9.5
  L1 - Top w0.125: U7.1@16.9,-7.9 v1(16.9,-8.425) 16.9,-8.75 17.25,-9.1 R36.1@17.575,-9.1
  L3 - Signal w0.125: v1(16.9,-8.425) 17.825,-8.425 18.1,-8.7 18.1,-12.9 18.8,-13.6 U8.101@20.123,-13.6
NetC17_2: C17.2 R12.2 U2.V6 | length 3.2
  L1 - Top w0.125: U2.V6@11.3,13.5 11.7,13.9 11.7,14.575 12.425,15.3 C17.2@12.425,15.638 R12.2@12.975,15.638
NetC84_1: C84.1 C85.1 U3.1 | length 2.9
  L1 - Top w0.3: C85.1@9.1,-15.725 C84.1@9.1,-14.9 10.1,-14.9 10.35,-14.65 U3.1@11.05,-14.65
NetC86_2: C86.2 C87.2 FB2.1 TP10.1 U3.2 | length 4.4
  L1 - Top w0.3: C86.2@10.7,-15.8 C87.2@11.55,-15.8 U3.2@11.55,-14.65
  L1 - Top w0.5: FB2.1@9.55,-16.55 v1(10.025,-15.8) C86.2@10.7,-15.8
  L6 - Bottom w0.4: v1(10.025,-15.8) TP10.1@10.825,-15.8
NetC104_2: C104.2 R57.2 U5.3 | length 2
  L1 - Top w0.125: R57.2@-8.563,18.25 U5.3@-6.55,18.25
NetL1_1: L1.1 U1.11 | length 1.5
  L1 - Top w0.3: L1.1@-13.85,6.95 U1.11@-13.85,8.4
NetL2_1: L2.1 R4.2 | length 1.4
  L1 - Top w0.3: R4.2@-17.175,1.688 -17.175,1.401 -16.999,1.225 L2.1@-16.125,1.225
NetL3_1: L3.1 U1.14 | length 1.5
  L1 - Top w0.3: L3.1@-12.35,6.9 U1.14@-12.35,8.4
NetL4_1: L4.1 U1.27 | length 1.5
  L1 - Top w0.3: U1.27@-12.35,13.4 L4.1@-12.35,14.875
NetL5_1: L5.1 R8.2 | length 1
  L1 - Top w0.3: L5.1@-9.1,15.55 R8.2@-9.1,16.588
NetL6_1: L6.1 U1.30 | length 1.4
  L1 - Top w0.3: U1.30@-13.85,13.4 L6.1@-13.85,14.85
NetR2_1: R2.1 U1.23 | length 2.1
  L1 - Top w0.125: U1.23@-10.6,12.15 -10.15,12.15 -9.15,13.15 R2.1@-8.912,13.15
NetR3_2: R3.2 U1.8 | length 1.4
  L1 - Top w0.2: R3.2@-17,9.15 U1.8@-15.6,9.15
NetR5_1: R5.1 U1.17 | length 3.7
  L1 - Top w0.125: U1.17@-10.6,9.15 -10.075,9.15 -9.775,8.85 -9.775,8.125 -9.45,7.8 -8.75,7.8 -8.425,7.475 R5.1@-8.425,7.037
NetR11_2: R11.2 U2.T2 | length 3.4
  L1 - Top w0.125: U2.T2@14.5,11.9 14.9,11.5 16.25,11.5 16.475,11.275 16.475,10.7 16.588,10.587 R11.2@17.025,10.587
NetR19_1: R19.1 U2.C19 | length 1.5
  L1 - Top w0.125: R19.1@-0.538,1.425 0.225,1.425 0.3,1.5 U2.C19@0.9,1.5
NetR22_2: R22.2 U3.9 | length 1
  L1 - Top w0.125: U3.9@14.25,-12.95 15.212,-12.95 R22.2@15.263,-13
NetR25_2: R25.2 U3.24 | length 1.1
  L1 - Top w0.125: R25.2@9.262,-14.05 9.625,-14.05 9.725,-13.95 U3.24@10.35,-13.95
NetR44_2: R44.2 U7.5 | length 1.1
  L1 - Top w0.1: U7.5@11.3,-4.05 11.312,-4.038 R44.2@11.312,-2.95
NetR45_2: R45.2 U7.2 | length 1.2
  L1 - Top w0.125: U7.2@16.9,-6.63 16.905,-6.625 R45.2@18.1,-6.625
NetR46_2: R46.2 U7.3 | length 1.2
  L1 - Top w0.125: U7.3@16.9,-5.36 16.902,-5.362 R46.2@18.075,-5.362
NetR47_2: R47.2 U7.7 | length 1.2
  L1 - Top w0.125: R47.2@10.15,-6.625 11.295,-6.625 U7.7@11.3,-6.63
NetR48_2: R48.2 U7.6 | length 4.1
  L1 - Top w0.125: R48.2@9.625,-5.675 9.625,-6.2 9.725,-6.3 10.475,-6.3 10.625,-6.15 10.625,-5.925 10.525,-5.825 10.15,-5.825 10.05,-5.725 10.05,-5.45 10.14,-5.36 U7.6@11.3,-5.36
NetR55_1: R55.1 U8.139 | length 3.1
  L1 - Top w0.125: R55.1@17.662,16.025 18.25,16.025 19.025,16.8 U8.139@20.4,16.8
NetR56_1: R56.1 U8.140 | length 2.9
  L1 - Top w0.125: R56.1@17.662,17.225 18.275,17.225 18.65,17.6 U8.140@20.4,17.6
NetR58_2: R58.2 U1.18 | length 1.9
  L1 - Top w0.125: U1.18@-10.6,9.65 -10,9.65 -9.9,9.55 -9.9,9.35 -9.775,9.225 -9.425,9.225 -9.337,9.138 R58.2@-9.337,8.8
NetR59_1: R59.1 U2.W11 | length 4
  L1 - Top w0.1: v1(6.9,13.9) U2.W11@7.3,14.3
  L1 - Top w0.125: v1(4.55,15.325) R59.1@4.55,15.85
  L3 - Signal w0.125: v1(4.55,15.325) 4.875,15.325 5.3,14.9 5.9,14.9 v1(6.9,13.9)
NRST: R25.1 U1.2 U2.W3 U8.7 | length 69.2
  L1 - Top w0.125: v1@-16.4,12.162 v1(-16.4,12.15) U1.2@-15.6,12.15 ; v1(8.1,-14.05) R25.1@8.738,-14.05 ; v1(13.3,13.9) U2.W3@13.7,14.3
  L3 - Signal w0.125: v1(-4.05,13.2) -1.025,16.225 4.55,16.225 5.55,15.225 6.975,15.225 8.7,13.5 ; v1(8.1,-14.05) 8.1,-13.6 6.375,-11.875 6.375,-8.375 6.875,-7.875 6.875,-1.375 6.55,-1.05 6.55,7.175 7.275,7.9 7.95,7.9 8.1,8.05 8.1,12.9 8.7,13.5 ; v1(13.3,13.9) 12.9,13.5 8.7,13.5
  L4 - Signal w0.125: U8.7@-20.4,13.6 -18.5,13.6 -17.05,12.15 v1(-16.4,12.15) -15.975,12.15 -15.6,12.525 -4.775,12.525 -4.1,13.2 v1(-4.05,13.2)
NRST_WILC_PA27: C106.2 R35.2 U2.M18 U4.7 | length 37.9
  L1 - Top w0.1: C106.2@-3.275,9.488 R35.2@-2.75,9.488 -2.388,9.488 -2.2,9.3 v1(-2.2,9)
  L1 - Top w0.125: v1(-5.55,-18.375) U4.7@-5.55,-17.14 ; v1(1.3,8.3) U2.M18@1.7,8.7
  L3 - Signal w0.125: v1(-5.55,-18.375) -4.925,-18.375 -4.45,-17.9 -3.75,-17.9 -3.4,-17.55 -2.825,-17.55 -2,-16.725 -2,-5.5 -3.15,-4.35 -3.15,2.7 -2.95,2.9 -2.95,7.85 -2.2,8.6 v1(-2.2,9)
  L6 - Bottom w0.125: v1(-2.2,9) -1.175,9 -0.875,8.7 0.9,8.7 v1(1.3,8.3)
nSTART_SOM: U1.24 U8.182 | length 10.6
  L1 - Top w0.15: U1.24@-10.58,12.62 -10.13,12.62 -9.45,13.3 v1(-9.45,14.8)
  L4 - Signal w0.125: U8.182@-13.6,20.4 -13.6,18.35 -10.05,14.8 v1(-9.45,14.8)
PA0: R59.2 U8.165 | length 11.1
  L1 - Top w0.125: U8.165@0,20.4 0,18.725 0.725,18 0.725,17.075 1.05,16.75 1.5,16.75 1.725,16.975 1.725,18.65 1.9,18.825 2.5,18.825 2.7,18.625 2.7,16.925 3.775,15.85 R59.2@4.025,15.85
PA1: U2.R9 U8.162 | length 16.2
  L1 - Top w0.125: v1(7.7,12.3) 9.075,12.3 9.325,12.05 9.325,11.525 U2.R9@8.9,11.1
  L4 - Signal w0.125: U8.162@2.4,20.4 2.4,19 2.875,18.525 7.05,18.525 7.8,17.775 7.8,15.5 8.475,14.825 8.475,13.075 v1(7.7,12.3)
PA2: U2.W12 U8.166 | length 12.4
  L1 - Top w0.125: U2.W12@6.5,14.3 v1(6.9,14.7)
  L4 - Signal w0.125: U8.166@-0.8,20.4 -0.8,19.025 0.825,17.4 5.775,17.4 6.9,16.275 v1(6.9,14.7)
PA3: U2.V11 U8.164 | length 12.1
  L1 - Top w0.125: U2.V11@7.3,13.5 v1(7.7,13.9)
  L4 - Signal w0.125: U8.164@0.8,20.4 0.8,19.025 2.05,17.775 5.85,17.775 7.2,16.425 7.2,15.05 7.7,14.55 v1(7.7,13.9)
PA4: U2.W14 U8.169 | length 11.2
  L1 - Top w0.125: U8.169@-3.2,20.4 -3.2,19.4 -2.25,18.45 -1.3,18.45 0.925,16.225 2.975,16.225 U2.W14@4.9,14.3
PA5: U2.V10 U8.163 | length 13.3
  L1 - Top w0.125: v1(7.7,13.1) U2.V10@8.1,13.5
  L4 - Signal w0.125: U8.163@1.6,20.4 1.6,19.025 2.475,18.15 6.825,18.15 7.5,17.475 7.5,15.25 8.1,14.65 8.1,13.5 v1(7.7,13.1)
PA6: U2.W15 U8.171 | length 12.2
  L1 - Top w0.125: U8.171@-4.8,20.4 -4.8,19.45 -4.575,19.225 -3.55,19.225 -2.45,18.125 -1.45,18.125 0.75,15.925 2.8,15.925 4.1,14.625 U2.W15@4.1,14.3
PA7: U2.W16 U8.173 | length 12.9
  L1 - Top w0.125: U8.173@-6.4,20.4 -6.4,19.325 -5.7,18.625 -4,18.625 -2.775,17.4 -1.6,17.4 0.475,15.325 2.275,15.325 U2.W16@3.3,14.3
PA8: U2.V12 U8.167 | length 14.2
  L1 - Top w0.125: U2.V12@6.5,13.5 v1(6.9,13.1)
  L4 - Signal w0.125: U8.167@-1.6,20.4 -1.6,18.8 0.2,17 2.575,17 3.775,15.8 5.225,15.8 6.725,14.3 7.075,14.3 7.3,14.075 7.3,13.5 v1(6.9,13.1)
